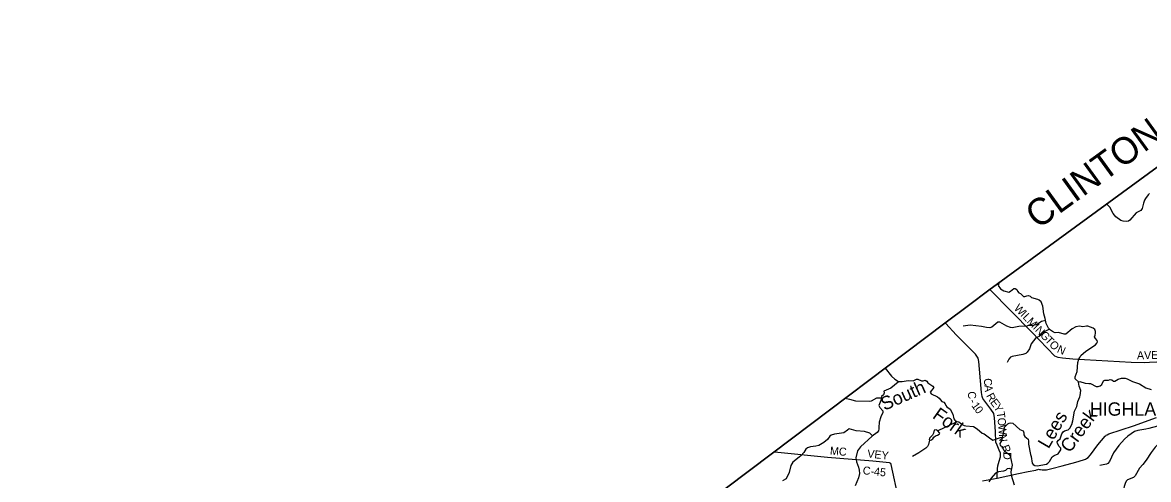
# Model space of a CAD drawing. Extents: x 1525783 to 1900577, y 218250 to 627376.
# Drawn here: x 1612574 to 1654768, y 488683 to 505801 of the extents above; entities that cross this region are included whole.
import ezdxf

# ---------------------------------------------------------------- set-up
doc = ezdxf.new("R2010")
doc.units = 0
for name, color, linetype in [('GM_X_Adjacent_County', 7, 'Continuous'), ('GM_X_Adjacent_County_Text', 7, 'Continuous'), ('GM_X_Corporation_Text', 7, 'Continuous'), ('GM_X_County', 7, 'Continuous'), ('GM_X_County_Road', 7, 'Continuous'), ('GM_X_County_Road_Text', 7, 'Continuous'), ('GM_X_Minor_Lake', 7, 'Continuous'), ('GM_X_Minor_River', 7, 'Continuous'), ('GM_X_Minor_River_Text', 7, 'Continuous'), ('GM_X_State_Route', 7, 'Continuous'), ('GM_X_Township', 7, 'Continuous')]:
    doc.layers.add(name, color=color, linetype=linetype)

msp = doc.modelspace()

# ---------------------------------------------------------------- linework, layer by layer
at = {"layer": 'GM_X_Adjacent_County'}
msp.add_lwpolyline([(1655741, 500852), (1648788, 495779), (1648023, 495203), (1647133, 494533), (1640676, 489672), (1638042, 487688), (1635644, 485883), (1633819, 484508), (1633505, 484272), (1633248, 484078), (1631413, 482696), (1628958, 480847), (1628919, 480818), (1621997, 475474), (1621966, 475451), (1620523, 474378), (1618604, 472952), (1614700, 470050), (1612987, 468763), (1608261, 465210)], dxfattribs=at)
at = {"layer": 'GM_X_County'}
msp.add_lwpolyline([(1608261, 465210), (1612987, 468763), (1614700, 470050), (1618604, 472952), (1620523, 474378), (1621966, 475451), (1621997, 475474), (1628919, 480818), (1628958, 480847), (1631413, 482696), (1633248, 484078), (1633505, 484272), (1633819, 484508), (1635644, 485883), (1638042, 487688), (1640676, 489672), (1647133, 494533), (1648023, 495203), (1648788, 495779), (1655741, 500852)], dxfattribs=at)
at = {"layer": 'GM_X_County_Road'}
for points in [[(1656355, 492137), (1656283, 492238), (1656122, 492498), (1656000, 492690), (1655875, 492819), (1655729, 492912), (1655570, 492973), (1655366, 493045), (1655229, 493084), (1655077, 493083), (1654801, 493067), (1654624, 493056), (1654114, 493069), (1651938, 493188), (1651549, 493226), (1651390, 493248), (1651258, 493307), (1650403, 494203), (1648840, 495785)], [(1649094, 488732), (1649093, 488835), (1649116, 489084), (1649128, 489195), (1649175, 489369), (1649222, 489527), (1649228, 489608), (1649220, 489663), (1649177, 489778), (1649097, 489962), (1649050, 490075), (1649038, 490484), (1648992, 490991), (1648970, 491157), (1648866, 491311), (1648634, 491621), (1648564, 491721), (1648534, 491786), (1648514, 491945), (1648441, 492811), (1648411, 493102), (1648384, 493231), (1648290, 493380), (1647562, 494100), (1647173, 494529)], [(1645416, 487921), (1645125, 489246), (1645108, 489276), (1645061, 489300), (1644438, 489367), (1642740, 489501), (1640756, 489709)]]:
    msp.add_lwpolyline(points, dxfattribs=at)
at = {"layer": 'GM_X_Minor_Lake'}
for points in [[(1646858, 490521), (1646807, 490544), (1646738, 490527), (1646713, 490412), (1646677, 490346), (1646562, 490230), (1646548, 490162), (1646618, 490157), (1646689, 490208), (1646730, 490269), (1646789, 490316), (1646856, 490341)], [(1646856, 490341), (1646923, 490382), (1646941, 490398), (1646953, 490416), (1646858, 490521)]]:
    msp.add_lwpolyline(points, dxfattribs=at)
at = {"layer": 'GM_X_Minor_River'}
for points in [[(1654812, 499392), (1654757, 499349), (1654659, 499208), (1654620, 499144), (1654576, 499034), (1654528, 498835), (1654477, 498763), (1654311, 498673), (1654073, 498394), (1654019, 498363), (1653944, 498352), (1653816, 498362), (1653738, 498389), (1653543, 498521), (1653439, 498645), (1653314, 498885), (1653205, 499001)], [(1649175, 496060), (1649133, 495953), (1649223, 495821), (1649346, 495749), (1649529, 495704), (1649602, 495737), (1649727, 495839), (1649777, 495840), (1649839, 495803), (1649854, 495739), (1649907, 495678), (1649973, 495655), (1650081, 495533), (1650139, 495532), (1650210, 495567), (1650276, 495576), (1650337, 495553), (1650391, 495488)], [(1652153, 492329), (1652022, 492453), (1652015, 492524), (1652093, 492725), (1652118, 493062), (1652156, 493190), (1652191, 493251), (1652232, 493321), (1652416, 493494), (1652779, 493726), (1652836, 493787), (1652857, 493843), (1652840, 493895), (1652777, 493958), (1652742, 494023), (1652765, 494091), (1652788, 494163), (1652785, 494231), (1652756, 494302), (1652695, 494357), (1652495, 494428), (1652445, 494431), (1652312, 494401), (1652186, 494431), (1652040, 494399), (1651909, 494323), (1651665, 494128), (1651604, 494123), (1651400, 494190), (1651272, 494182), (1651212, 494197), (1651094, 494277), (1651027, 494348), (1650940, 494522), (1650902, 494717), (1650847, 494883), (1650807, 495176), (1650747, 495336), (1650678, 495403), (1650622, 495426), (1650391, 495488)], [(1650434, 494450), (1650258, 494455), (1650206, 494426), (1649913, 494411), (1649654, 494369), (1649598, 494371), (1649463, 494432), (1649193, 494578), (1649125, 494581), (1648898, 494388), (1648825, 494364), (1648693, 494374), (1648506, 494415), (1648080, 494459), (1647819, 494425)], [(1650916, 494644), (1650758, 494595), (1650567, 494476), (1650434, 494450)], [(1651059, 494315), (1650836, 494207), (1650775, 494158), (1650736, 494090), (1650667, 494039), (1650544, 493985), (1650369, 493765)], [(1650369, 493765), (1650304, 493573), (1650228, 493458), (1650173, 493405), (1650059, 493365), (1649655, 493293), (1649601, 493268), (1649533, 493193), (1649477, 493070)], [(1644899, 492850), (1645135, 492559), (1645257, 492445), (1645398, 492355), (1645538, 492354), (1645767, 492387), (1645955, 492382), (1646074, 492436), (1646128, 492441), (1646261, 492383), (1646327, 492374), (1646394, 492401), (1646461, 492366), (1646500, 492297), (1646693, 492184), (1646724, 492124), (1646593, 491959), (1646626, 491891), (1646858, 491781), (1646928, 491728), (1647030, 491606), (1647101, 491577), (1647149, 491522), (1647176, 491460), (1647209, 491405), (1647331, 491313), (1647433, 491133), (1647478, 490960), (1647517, 490906), (1647586, 490857), (1647658, 490839), (1647787, 490737), (1647856, 490706), (1647918, 490687), (1648208, 490665), (1648353, 490576), (1648537, 490423), (1648612, 490394), (1648806, 490245), (1648939, 490159), (1649221, 490252), (1649291, 490259), (1649328, 490333), (1649369, 490648), (1649501, 490763), (1649551, 490792), (1649608, 490807), (1649682, 490790), (1649944, 490561), (1650073, 490499), (1650098, 490425), (1650101, 490357), (1650138, 490288), (1650255, 490188), (1650266, 490120), (1650270, 490000), (1650347, 489620)], [(1650347, 489620), (1650377, 489538), (1650410, 489296), (1650443, 489244), (1650515, 489206), (1650593, 489197), (1650948, 489260), (1651000, 489289), (1651058, 489357), (1651157, 489536), (1651228, 489585), (1651389, 489640), (1651486, 489789), (1651487, 489860), (1651420, 489915), (1651353, 490034), (1651352, 490088), (1651395, 490154), (1651455, 490205), (1651520, 490393), (1651571, 490462), (1651626, 490505), (1651757, 490546), (1651826, 490607), (1651893, 490740), (1651937, 490880), (1651997, 491238), (1652084, 491419), (1652115, 491605), (1652194, 491773), (1652209, 491829), (1652230, 492011), (1652166, 492184), (1652140, 492323), (1652201, 492350), (1652401, 492287), (1652535, 492277), (1652596, 492280), (1652807, 492164), (1652883, 492161), (1652956, 492186), (1653021, 492235), (1653083, 492373), (1653134, 492400), (1653265, 492408), (1653335, 492429), (1653399, 492412), (1653455, 492361), (1653505, 492364), (1653635, 492439), (1653762, 492473), (1653896, 492473), (1653974, 492449), (1654174, 492348), (1654434, 492268), (1654674, 492114), (1654866, 492054)], [(1645398, 492355), (1645389, 492325), (1645114, 492109), (1644852, 491997), (1644865, 491926), (1644833, 491855), (1644768, 491788), (1644740, 491646), (1644659, 491453), (1644698, 491374), (1644816, 491258), (1644813, 491188), (1644734, 491035), (1644675, 490834), (1644664, 490634), (1644663, 490584), (1644652, 490504), (1644599, 490437), (1644414, 490305), (1643972, 489906), (1643865, 489761), (1643805, 489494), (1643823, 489345), (1643904, 489144), (1643930, 489027), (1643936, 488907), (1643901, 488739), (1643780, 488445)], [(1644757, 491729), (1644573, 491723), (1644371, 491618), (1644313, 491603), (1643807, 491616), (1643571, 491679), (1643390, 491713)], [(1647563, 490873), (1647508, 490810), (1647112, 490622), (1646873, 490506)], [(1655669, 491105), (1655345, 490972), (1655232, 490771), (1655108, 490685), (1654779, 490595), (1654666, 490563), (1654368, 490515), (1654241, 490477), (1653997, 490304), (1653871, 490190), (1653662, 489950), (1653453, 489677), (1653303, 489352), (1653250, 489285), (1653197, 489257), (1653129, 489240), (1652943, 489205)], [(1644427, 490314), (1644322, 490415), (1644123, 490476), (1643819, 490503), (1643554, 490585), (1643487, 490536), (1643355, 490436), (1642996, 490380), (1642881, 490337), (1642831, 490302), (1642739, 490185), (1642605, 490063), (1642415, 489960), (1642298, 489928), (1642100, 489907), (1641989, 489867), (1641932, 489819), (1641852, 489695), (1641740, 489574), (1641679, 489517), (1641444, 489334), (1641368, 489210), (1641306, 488950), (1641190, 488708), (1641059, 488632)], [(1656199, 490672), (1656161, 490576), (1656099, 490515), (1656029, 490488), (1655834, 490491), (1655690, 490439), (1655264, 490140), (1655019, 489893), (1654863, 489689), (1654682, 489405), (1654551, 489247), (1654432, 489104), (1654267, 488824), (1654206, 488758), (1653981, 488668), (1653928, 488614), (1653889, 488535), (1653863, 488425), (1653850, 488355), (1653850, 488252), (1653885, 488135), (1654041, 487952), (1654241, 487785)], [(1646563, 490161), (1646522, 489988), (1646489, 489923), (1646424, 489859), (1646162, 489679), (1645920, 489539)], [(1649291, 490259), (1649277, 490159), (1649197, 490026), (1649214, 489960), (1649285, 489913), (1649341, 489792), (1649400, 489727), (1649531, 489637), (1649582, 489568), (1649619, 489393), (1649655, 489220), (1649607, 488967), (1649627, 488844), (1649729, 488476)], [(1649627, 489075), (1649543, 489098), (1649472, 489077), (1649411, 489024), (1649337, 488997), (1649148, 488968), (1649041, 488919), (1648878, 488730), (1648784, 488589)]]:
    msp.add_lwpolyline(points, dxfattribs=at)
at = {"layer": 'GM_X_State_Route'}
msp.add_lwpolyline([(1648547, 488628), (1649094, 488732), (1649894, 488901), (1650262, 488978), (1650541, 489033), (1650576, 489045), (1650627, 489062), (1650650, 489063), (1650680, 489059), (1650725, 489054), (1650782, 489045), (1650890, 489040), (1650947, 489042), (1651152, 489094), (1651531, 489188), (1652043, 489329), (1652330, 489413), (1652408, 489443), (1652451, 489465), (1652506, 489508), (1652591, 489601), (1652871, 489979), (1653005, 490145), (1653142, 490306), (1653165, 490323), (1653188, 490341), (1653215, 490356), (1653284, 490387), (1654201, 490698), (1655074, 491008)], dxfattribs=at)
at = {"layer": 'GM_X_Township'}
msp.add_lwpolyline([(1656342, 482882), (1650243, 482694), (1649454, 482702), (1649095, 482859), (1640142, 486770), (1638042, 487688), (1640676, 489672), (1647133, 494533), (1648023, 495203), (1648788, 495779), (1655741, 500852)], dxfattribs=at)

# ---------------------------------------------------------------- texts
at = {"layer": 'GM_X_Adjacent_County_Text'}
msp.add_text('CLINTON COUNTY', height=1000, rotation=35.9139, dxfattribs=at).set_placement((1650624, 498036))
at = {"layer": 'GM_X_Corporation_Text'}
msp.add_text('HIGHLAND', height=500, rotation=0, dxfattribs=at).set_placement((1652568, 491072))
at = {"layer": 'GM_X_County_Road_Text'}
for s, rotation, p in [('W', 314.0208, (1649708, 495079)), ('I', 314.0235, (1649950, 494829)), ('L', 314.0196, (1650036, 494741)), ('M', 314.02, (1650192, 494580)), ('I', 314.0202, (1650418, 494345)), ('N', 314.0221, (1650503, 494257)), ('G', 314.0211, (1650687, 494067)), ('T', 314.0196, (1650870, 493877)), ('O', 314.1335, (1651027, 493715)), ('N', 336.911, (1651317, 493453)), ('AVE', 1.2489, (1654339, 493183)), ('C', 274.8103, (1648594, 492462)), ('A', 274.8589, (1648615, 492216)), ('C', 274.8748, (1647995, 491971)), ('-', 292.1278, (1648039, 491630)), ('R', 299.0416, (1648677, 491822)), ('E', 306.6328, (1648820, 491570)), ('1', 304.7839, (1648120, 491452)), ('0', 307.2559, (1648233, 491289)), ('Y', 301.4876, (1648950, 491396)), ('T', 278.521, (1649077, 491200)), ('O', 275.608, (1649110, 490982)), ('W', 274.0233, (1649136, 490722)), ('N', 273.6597, (1649160, 490375)), ('MC', 355.6021, (1642823, 489614)), ('R', 291.2705, (1649247, 489913)), ('VEY', 354.0084, (1644219, 489508)), ('D', 269.3279, (1649331, 489713)), ('C-45', 354.2899, (1644050, 488880))]:
    msp.add_text(s, height=300, rotation=rotation, dxfattribs=at).set_placement(p)
at = {"layer": 'GM_X_Minor_River_Text'}
for s, rotation, p in [('South', 23.7431, (1644871, 491251)), ('Fork', 324.6704, (1646641, 491008)), ('Lees', 59.743, (1651022, 489806)), ('Creek', 53.7431, (1651825, 489651))]:
    msp.add_text(s, height=500, rotation=rotation, dxfattribs=at).set_placement(p)

doc.saveas('drawing.dxf')
